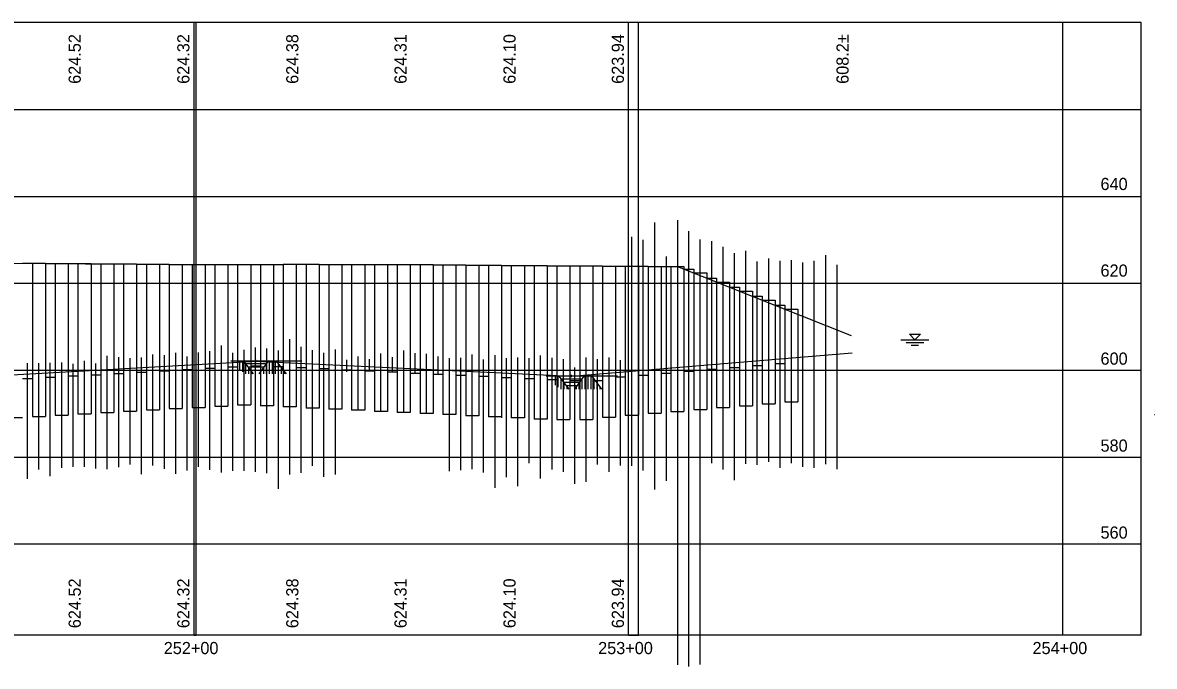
# Model space of a CAD drawing. Extents: x 2267596 to 2268160, y 713755 to 714793.
# Drawn here: x 2267899.2 to 2268159.8, y 713755.1 to 713903.3 of the extents above; entities that cross this region are included whole.
import ezdxf

# ---------------------------------------------------------------- set-up
doc = ezdxf.new("R2010")
doc.units = 0
for name, color, linetype in [('BR_P_Gen_Text', 7, 'Continuous'), ('BR_P_Sub_Deep_Object', 7, 'Continuous'), ('Default', 7, 'Continuous'), ('GE_X_Alignment', 7, 'Continuous'), ('PF_X_Ground_Line', 7, 'Continuous'), ('SC_Scratch1', 7, 'Continuous'), ('SC_Scratch3', 7, 'Continuous'), ('SC_Scratch9', 7, 'Continuous'), ('SH_Major_Grid_Line', 7, 'Continuous'), ('UT_P_Water_Cells', 7, 'Continuous'), ('XS_X_Ground_Line', 7, 'Continuous')]:
    doc.layers.add(name, color=color, linetype=linetype)

msp = doc.modelspace()

# ---------------------------------------------------------------- linework, layer by layer
at = {"layer": 'BR_P_Sub_Deep_Object'}
for p, q in [((2267899.24, 713847.93), (2267901.49, 713847.93)), ((2267901.49, 713847.93), (2267901.49, 713812.68)), ((2267901.49, 713847.92), (2267904.49, 713847.92)), ((2267904.49, 713847.92), (2267904.49, 713812.68)), ((2267904.49, 713847.9), (2267906.74, 713847.9)), ((2267906.74, 713847.9), (2267906.74, 713812.98)), ((2267906.74, 713847.88), (2267909.74, 713847.88)), ((2267909.74, 713847.88), (2267909.74, 713812.98)), ((2267909.74, 713847.86), (2267911.99, 713847.86)), ((2267911.99, 713847.86), (2267911.99, 713813.27)), ((2267911.99, 713847.85), (2267914.99, 713847.85)), ((2267914.99, 713847.85), (2267914.99, 713813.27)), ((2267914.99, 713847.82), (2267917.24, 713847.82)), ((2267917.24, 713847.82), (2267917.24, 713813.57)), ((2267917.24, 713847.81), (2267920.24, 713847.81)), ((2267920.24, 713847.81), (2267920.24, 713813.57)), ((2267920.24, 713847.78), (2267922.49, 713847.78)), ((2267922.49, 713847.78), (2267922.49, 713813.87)), ((2267922.49, 713847.76), (2267925.49, 713847.76)), ((2267925.49, 713847.76), (2267925.49, 713813.87)), ((2267925.49, 713847.74), (2267927.74, 713847.74)), ((2267927.74, 713847.74), (2267927.74, 713814.16)), ((2267927.74, 713847.72), (2267930.74, 713847.72)), ((2267930.74, 713847.72), (2267930.74, 713814.16)), ((2267930.74, 713847.7), (2267932.99, 713847.7)), ((2267932.99, 713847.7), (2267932.99, 713814.46)), ((2267932.99, 713847.68), (2267935.99, 713847.68)), ((2267935.99, 713847.68), (2267935.99, 713814.46)), ((2267935.99, 713847.66), (2267938.24, 713847.66)), ((2267938.24, 713847.66), (2267938.24, 713814.75)), ((2267938.24, 713847.64), (2267941.24, 713847.64)), ((2267941.24, 713847.64), (2267941.24, 713814.75)), ((2267941.24, 713847.64), (2267943.49, 713847.64)), ((2267943.49, 713847.65), (2267943.49, 713815.05)), ((2267943.49, 713847.65), (2267946.49, 713847.65)), ((2267946.49, 713847.66), (2267946.49, 713815.05)), ((2267946.49, 713847.66), (2267948.74, 713847.66)), ((2267948.74, 713847.66), (2267948.74, 713815.34)), ((2267948.74, 713847.66), (2267951.74, 713847.66)), ((2267951.74, 713847.67), (2267951.74, 713815.34)), ((2267951.74, 713847.67), (2267953.99, 713847.67)), ((2267953.99, 713847.68), (2267953.99, 713815.11)), ((2267953.99, 713847.68), (2267956.99, 713847.68)), ((2267956.99, 713847.68), (2267956.99, 713815.11)), ((2267956.99, 713847.68), (2267959.24, 713847.68)), ((2267959.24, 713847.69), (2267959.24, 713814.86)), ((2267959.24, 713847.69), (2267962.24, 713847.69)), ((2267962.24, 713847.69), (2267962.24, 713814.86)), ((2267962.24, 713847.69), (2267964.49, 713847.69)), ((2267964.49, 713847.69), (2267964.49, 713814.6)), ((2267964.49, 713847.69), (2267967.49, 713847.69)), ((2267967.49, 713847.69), (2267967.49, 713814.6)), ((2267967.49, 713847.68), (2267969.74, 713847.68)), ((2267969.74, 713847.68), (2267969.74, 713814.35)), ((2267969.74, 713847.68), (2267972.74, 713847.68)), ((2267972.74, 713847.68), (2267972.74, 713814.35)), ((2267972.74, 713847.67), (2267974.99, 713847.67)), ((2267974.99, 713847.67), (2267974.99, 713814.1)), ((2267974.99, 713847.66), (2267977.99, 713847.66)), ((2267977.99, 713847.66), (2267977.99, 713814.1)), ((2267977.99, 713847.65), (2267980.24, 713847.65)), ((2267980.24, 713847.65), (2267980.24, 713813.84)), ((2267980.24, 713847.65), (2267983.24, 713847.65)), ((2267983.24, 713847.65), (2267983.24, 713813.84)), ((2267983.24, 713847.64), (2267985.49, 713847.64)), ((2267985.49, 713847.64), (2267985.49, 713813.59)), ((2267985.49, 713847.63), (2267988.49, 713847.63)), ((2267988.49, 713847.63), (2267988.49, 713813.59)), ((2267988.49, 713847.62), (2267990.74, 713847.62)), ((2267990.74, 713847.62), (2267990.74, 713813.34)), ((2267990.74, 713847.61), (2267993.74, 713847.61)), ((2267993.74, 713847.61), (2267993.74, 713813.34)), ((2267993.74, 713847.58), (2267995.99, 713847.58)), ((2267995.99, 713847.58), (2267995.99, 713813.09)), ((2267995.99, 713847.56), (2267998.99, 713847.56)), ((2267998.99, 713847.56), (2267998.99, 713813.09)), ((2267998.99, 713847.54), (2268001.24, 713847.54)), ((2268001.24, 713847.54), (2268001.24, 713812.83)), ((2268001.24, 713847.52), (2268004.24, 713847.52)), ((2268004.24, 713847.52), (2268004.24, 713812.83)), ((2268004.24, 713847.49), (2268006.49, 713847.49)), ((2268006.49, 713847.49), (2268006.49, 713812.58)), ((2268006.49, 713847.47), (2268009.49, 713847.47)), ((2268009.49, 713847.47), (2268009.49, 713812.33)), ((2268009.49, 713847.45), (2268011.74, 713847.45)), ((2268011.74, 713847.45), (2268011.74, 713812.33)), ((2268011.74, 713847.43), (2268014.74, 713847.43)), ((2268014.74, 713847.43), (2268014.74, 713812.33)), ((2268014.74, 713847.41), (2268016.99, 713847.41)), ((2268016.99, 713847.41), (2268016.99, 713812.07)), ((2268016.99, 713847.39), (2268019.99, 713847.39)), ((2268019.99, 713847.39), (2268019.99, 713812.07)), ((2268019.99, 713847.37), (2268022.24, 713847.37)), ((2268022.24, 713847.37), (2268022.24, 713811.93)), ((2268022.24, 713847.36), (2268025.24, 713847.36)), ((2268025.24, 713847.36), (2268025.24, 713811.93)), ((2268025.24, 713847.34), (2268027.49, 713847.34)), ((2268027.49, 713847.34), (2268027.49, 713811.93)), ((2268027.49, 713847.33), (2268030.49, 713847.33)), ((2268030.49, 713847.33), (2268030.49, 713811.93)), ((2268030.49, 713847.31), (2268032.74, 713847.31)), ((2268032.74, 713847.31), (2268032.74, 713812.51)), ((2268032.74, 713847.29), (2268035.74, 713847.29)), ((2268035.74, 713847.29), (2268035.74, 713812.51)), ((2268035.74, 713847.27), (2268037.99, 713847.27)), ((2268037.99, 713847.27), (2268037.99, 713812.95)), ((2268037.99, 713847.26), (2268040.99, 713847.26)), ((2268040.99, 713847.26), (2268040.99, 713812.95)), ((2268040.99, 713847.24), (2268043.24, 713847.24)), ((2268043.24, 713847.24), (2268043.24, 713813.39)), ((2268043.24, 713847.22), (2268046.24, 713847.22)), ((2268046.24, 713847.22), (2268046.24, 713813.39)), ((2268046.24, 713847.21), (2268048.49, 713847.21)), ((2268048.49, 713847.21), (2268048.49, 713813.83)), ((2268048.49, 713847.18), (2268051.49, 713847.18)), ((2268051.49, 713847.18), (2268051.49, 713813.83)), ((2268051.49, 713846.59), (2268053.74, 713846.59)), ((2268053.74, 713846.59), (2268053.74, 713814.27)), ((2268053.74, 713845.69), (2268056.74, 713845.69)), ((2268056.74, 713845.69), (2268056.74, 713814.27)), ((2268056.74, 713844.5), (2268058.99, 713844.5)), ((2268058.99, 713844.5), (2268058.99, 713814.7)), ((2268058.99, 713843.61), (2268061.99, 713843.61)), ((2268061.99, 713843.61), (2268061.99, 713814.7)), ((2268061.99, 713842.42), (2268064.24, 713842.42)), ((2268064.24, 713842.42), (2268064.24, 713815.14)), ((2268064.24, 713841.53), (2268067.24, 713841.53)), ((2268067.24, 713841.53), (2268067.24, 713815.14)), ((2268067.24, 713840.34), (2268069.49, 713840.34)), ((2268069.49, 713840.34), (2268069.49, 713815.58)), ((2268069.49, 713839.45), (2268072.49, 713839.45)), ((2268072.49, 713839.45), (2268072.49, 713815.58)), ((2268072.49, 713838.26), (2268074.74, 713838.26)), ((2268074.74, 713838.26), (2268074.74, 713816.02)), ((2268074.74, 713837.36), (2268077.74, 713837.36)), ((2268077.74, 713837.36), (2268077.74, 713816.02)), ((2268072.49, 713824.83), (2268074.74, 713824.83)), ((2267909.74, 713821.98), (2267911.99, 713821.98)), ((2267914.99, 713822.27), (2267917.24, 713822.27)), ((2267920.24, 713822.57), (2267922.49, 713822.57)), ((2267925.49, 713822.87), (2267927.74, 713822.87)), ((2267930.74, 713823.16), (2267932.99, 713823.16)), ((2267935.99, 713823.46), (2267938.24, 713823.46)), ((2267941.24, 713823.75), (2267943.49, 713823.75)), ((2267946.49, 713824.05), (2267948.74, 713824.05)), ((2267951.74, 713824.34), (2267953.99, 713824.34)), ((2267959.24, 713824.11), (2267956.99, 713824.11)), ((2267964.49, 713823.86), (2267962.24, 713823.86)), ((2267969.74, 713823.6), (2267967.49, 713823.6)), ((2267974.99, 713823.35), (2267972.74, 713823.35)), ((2267980.24, 713823.1), (2267977.99, 713823.1)), ((2267985.49, 713822.84), (2267983.24, 713822.84)), ((2267990.74, 713822.59), (2267988.49, 713822.59)), ((2267995.99, 713822.34), (2267993.74, 713822.34)), ((2268001.24, 713822.09), (2267998.99, 713822.09)), ((2268040.99, 713822.2), (2268043.24, 713822.2)), ((2268046.24, 713822.64), (2268048.49, 713822.64)), ((2268051.49, 713823.08), (2268053.74, 713823.08)), ((2268056.74, 713823.52), (2268058.99, 713823.52)), ((2268061.99, 713823.96), (2268064.24, 713823.96)), ((2268067.24, 713824.39), (2268069.49, 713824.39)), ((2267899.24, 713821.39), (2267901.49, 713821.39)), ((2267904.49, 713821.68), (2267906.74, 713821.68)), ((2268006.49, 713821.83), (2268004.24, 713821.83)), ((2268011.74, 713821.58), (2268009.49, 713821.58)), ((2268016.99, 713821.33), (2268014.74, 713821.33)), ((2268022.24, 713821.07), (2268019.99, 713821.07)), ((2268025.24, 713820.93), (2268027.49, 713820.93)), ((2268030.49, 713820.93), (2268032.74, 713820.93)), ((2268035.74, 713821.76), (2268037.99, 713821.76)), ((2267927.74, 713814.16), (2267930.74, 713814.16)), ((2267932.99, 713814.46), (2267935.99, 713814.46)), ((2267938.24, 713814.75), (2267941.24, 713814.75)), ((2267943.49, 713815.05), (2267946.49, 713815.05)), ((2267948.74, 713815.34), (2267951.74, 713815.34)), ((2267956.99, 713815.11), (2267953.99, 713815.11)), ((2267962.24, 713814.86), (2267959.24, 713814.86)), ((2267967.49, 713814.6), (2267964.49, 713814.6)), ((2267972.74, 713814.35), (2267969.74, 713814.35)), ((2268053.74, 713814.27), (2268056.74, 713814.27)), ((2268058.99, 713814.7), (2268061.99, 713814.7)), ((2268064.24, 713815.14), (2268067.24, 713815.14)), ((2268069.49, 713815.58), (2268072.49, 713815.58)), ((2268074.74, 713816.02), (2268077.74, 713816.02)), ((2267896.24, 713812.39), (2267899.24, 713812.39)), ((2267901.49, 713812.68), (2267904.49, 713812.68)), ((2267906.74, 713812.98), (2267909.74, 713812.98)), ((2267911.99, 713813.27), (2267914.99, 713813.27)), ((2267917.24, 713813.57), (2267920.24, 713813.57)), ((2267922.49, 713813.87), (2267925.49, 713813.87)), ((2267977.99, 713814.1), (2267974.99, 713814.1)), ((2267983.24, 713813.84), (2267980.24, 713813.84)), ((2267988.49, 713813.59), (2267985.49, 713813.59)), ((2267993.74, 713813.34), (2267990.74, 713813.34)), ((2267998.99, 713813.09), (2267995.99, 713813.09)), ((2268004.24, 713812.83), (2268001.24, 713812.83)), ((2268009.49, 713812.58), (2268006.49, 713812.58)), ((2268014.74, 713812.33), (2268011.74, 713812.33)), ((2268019.99, 713812.07), (2268016.99, 713812.07)), ((2268022.24, 713811.93), (2268025.24, 713811.93)), ((2268027.49, 713811.93), (2268030.49, 713811.93)), ((2268032.74, 713812.51), (2268035.74, 713812.51)), ((2268037.99, 713812.95), (2268040.99, 713812.95)), ((2268043.24, 713813.39), (2268046.24, 713813.39)), ((2268048.49, 713813.83), (2268051.49, 713813.83))]:
    msp.add_line(p, q, dxfattribs=at)
at = {"layer": 'Default'}
for p, q in [((2267963.53, 713825.41), (2267947.14, 713825.41)), ((2267949.16, 713825.41), (2267949.16, 713823.35)), ((2267949.85, 713825.41), (2267949.85, 713822.92)), ((2267950.06, 713825.41), (2267952.34, 713822.46)), ((2267950.54, 713824.8), (2267950.54, 713822.46)), ((2267955.31, 713824.77), (2267950.54, 713824.77)), ((2267955.77, 713825.41), (2267953.64, 713822.46)), ((2267955.31, 713824.77), (2267955.31, 713822.46)), ((2267956, 713825.41), (2267956, 713822.46)), ((2267956.69, 713825.41), (2267956.69, 713822.46)), ((2267957.38, 713825.41), (2267957.38, 713822.46)), ((2267957.6, 713825.41), (2267959.88, 713822.46)), ((2267958.07, 713824.8), (2267958.07, 713822.46)), ((2267954.76, 713824.01), (2267951.14, 713824.01)), ((2267951.23, 713823.9), (2267951.23, 713822.46)), ((2267954.19, 713823.22), (2267951.75, 713823.22)), ((2267951.91, 713823.02), (2267951.91, 713822.46)), ((2267954.01, 713822.97), (2267954.01, 713822.46)), ((2267954.66, 713823.87), (2267954.66, 713822.46)), ((2267958.76, 713823.9), (2267958.76, 713822.46)), ((2267959.45, 713823.02), (2267959.45, 713822.46)), ((2268036.18, 713821.91), (2268019.79, 713821.91)), ((2268021.8, 713821.91), (2268021.8, 713819.85)), ((2268022.49, 713821.91), (2268022.49, 713819.42)), ((2268022.71, 713821.91), (2268024.99, 713818.96)), ((2268023.18, 713821.3), (2268023.18, 713818.96)), ((2268027.96, 713821.27), (2268023.18, 713821.27)), ((2268027.4, 713820.51), (2268023.79, 713820.51)), ((2268023.87, 713820.4), (2268023.87, 713818.96)), ((2268026.83, 713819.72), (2268024.4, 713819.72)), ((2268024.56, 713819.52), (2268024.56, 713818.96)), ((2268028.42, 713821.91), (2268026.28, 713818.96)), ((2268026.65, 713819.47), (2268026.65, 713818.96)), ((2268027.3, 713820.37), (2268027.3, 713818.96)), ((2268027.96, 713821.27), (2268027.96, 713818.96)), ((2268028.65, 713821.91), (2268028.65, 713818.96)), ((2268029.34, 713821.91), (2268029.34, 713818.96)), ((2268030.03, 713821.91), (2268030.03, 713818.96)), ((2268030.25, 713821.91), (2268032.52, 713818.96)), ((2268030.72, 713821.3), (2268030.72, 713818.96)), ((2268031.41, 713820.4), (2268031.41, 713818.96)), ((2268032.09, 713819.52), (2268032.09, 713818.96))]:
    msp.add_line(p, q, dxfattribs=at)
at = {"layer": 'GE_X_Alignment'}
for p, q in [((2267938.74, 713762.33), (2267938.74, 713903.31)), ((2268038.74, 713762.33), (2268038.74, 713903.31)), ((2268138.74, 713762.33), (2268138.74, 713903.31)), ((2267595.7, 713883.31), (2268156.77, 713883.31)), ((2267595.7, 713863.31), (2268156.77, 713863.31)), ((2267595.7, 713843.31), (2268156.77, 713843.31)), ((2267595.7, 713823.31), (2268156.77, 713823.31)), ((2267595.7, 713803.31), (2268156.77, 713803.31)), ((2267595.7, 713783.31), (2268156.77, 713783.31))]:
    msp.add_line(p, q, dxfattribs=at)
at = {"layer": 'PF_X_Ground_Line'}
msp.add_line((2268159.73, 713813.12), (2268159.78, 713813.12), dxfattribs=at)
at = {"layer": 'SC_Scratch1'}
for p, q in [((2268044.74, 713857.29), (2268044.74, 713795.88)), ((2268049.99, 713857.86), (2268049.99, 713755.47)), ((2268039.49, 713801.27), (2268039.49, 713854)), ((2268042.12, 713800.26), (2268042.12, 713853.32)), ((2268052.62, 713755.14), (2268052.62, 713855.34)), ((2268055.24, 713755.59), (2268055.24, 713853.42)), ((2268057.87, 713801.92), (2268057.87, 713853.02)), ((2268060.49, 713800.48), (2268060.49, 713851.68)), ((2268065.74, 713801.77), (2268065.74, 713850.75)), ((2268047.37, 713849.46), (2268047.37, 713797.82)), ((2268063.12, 713797.98), (2268063.12, 713850.22)), ((2268068.37, 713801.55), (2268068.37, 713848.35)), ((2268070.99, 713802.23), (2268070.99, 713849.02)), ((2268073.62, 713800.86), (2268073.62, 713848.48)), ((2268076.24, 713801.88), (2268076.24, 713848.62)), ((2268078.87, 713801.08), (2268078.87, 713848.08)), ((2268081.49, 713800.83), (2268081.49, 713848.48)), ((2268084.12, 713801.68), (2268084.12, 713849.82)), ((2268086.74, 713800.54), (2268086.74, 713847.55)), ((2267960.74, 713799.28), (2267960.74, 713830.44)), ((2267934.49, 713799.49), (2267934.49, 713827.3)), ((2267939.74, 713801.05), (2267939.74, 713827.35)), ((2267942.37, 713800.35), (2267942.37, 713827.67)), ((2267944.99, 713799.8), (2267944.99, 713829.03)), ((2267947.62, 713800.17), (2267947.62, 713827.33)), ((2267950.24, 713800.17), (2267950.24, 713828.02)), ((2267952.87, 713799.89), (2267952.87, 713828.5)), ((2267955.49, 713799.62), (2267955.49, 713828.29)), ((2267958.12, 713795.99), (2267958.12, 713827.83)), ((2267963.37, 713799.66), (2267963.37, 713828.71)), ((2267965.99, 713801.28), (2267965.99, 713827.92)), ((2267968.62, 713798.78), (2267968.62, 713827.3)), ((2267971.24, 713799.28), (2267971.24, 713828.07)), ((2267986.99, 713813.59), (2267986.99, 713827.81)), ((2267989.62, 713822.59), (2267989.62, 713827.26)), ((2267900.37, 713798.29), (2267900.37, 713824.9)), ((2267902.99, 713800.47), (2267902.99, 713824.9)), ((2267905.62, 713798.89), (2267905.62, 713825.01)), ((2267908.24, 713800.85), (2267908.24, 713825.11)), ((2267910.87, 713801.04), (2267910.87, 713824.74)), ((2267913.49, 713801.07), (2267913.49, 713825.48)), ((2267916.12, 713800.71), (2267916.12, 713824.85)), ((2267918.74, 713800.53), (2267918.74, 713826.61)), ((2267921.37, 713801.02), (2267921.37, 713826.3)), ((2267923.99, 713801.64), (2267923.99, 713826.09)), ((2267926.62, 713799.36), (2267926.62, 713826.25)), ((2267929.24, 713801.39), (2267929.24, 713826.93)), ((2267931.87, 713800.59), (2267931.87, 713826.77)), ((2267937.12, 713800.22), (2267937.12, 713826.46)), ((2267973.87, 713822.96), (2267973.87, 713825.72)), ((2267976.49, 713814.1), (2267976.49, 713826.48)), ((2267979.12, 713823.1), (2267979.12, 713825.85)), ((2267981.74, 713813.84), (2267981.74, 713827.17)), ((2267984.37, 713822.84), (2267984.37, 713826.33)), ((2267992.24, 713813.34), (2267992.24, 713827.08)), ((2267994.87, 713822.34), (2267994.87, 713826.44)), ((2267997.49, 713800.1), (2267997.49, 713826.07)), ((2268000.12, 713800.28), (2268000.12, 713826.16)), ((2268002.74, 713800.56), (2268002.74, 713826.9)), ((2268005.37, 713799.76), (2268005.37, 713825.8)), ((2268007.99, 713796.27), (2268007.99, 713826.8)), ((2268010.62, 713798.7), (2268010.62, 713826.07)), ((2268013.24, 713796.64), (2268013.24, 713826.25)), ((2268015.87, 713801.9), (2268015.87, 713826.07)), ((2268018.49, 713798.38), (2268018.49, 713826.71)), ((2268021.12, 713800.46), (2268021.12, 713826.15)), ((2268023.74, 713799.93), (2268023.74, 713825.89)), ((2268028.99, 713797.62), (2268028.99, 713826.24)), ((2268031.62, 713801.62), (2268031.62, 713825.87)), ((2268034.24, 713799.91), (2268034.24, 713826.27)), ((2268036.87, 713801.34), (2268036.87, 713825.61)), ((2268026.37, 713797.19), (2268026.37, 713823.91))]:
    msp.add_line(p, q, dxfattribs=at)
at = {"layer": 'SC_Scratch3'}
for p, q in [((2267939.21, 713762.33), (2267939.21, 713903.31)), ((2268041.06, 713762.33), (2268041.06, 713903.31)), ((2267938.74, 713762.33), (2267939.21, 713762.33)), ((2268038.74, 713762.33), (2268041.06, 713762.33))]:
    msp.add_line(p, q, dxfattribs=at)
at = {"layer": 'SC_Scratch9'}
for p, q in [((2267952.95, 713825.19), (2267952.95, 713825.72)), ((2268025.6, 713821.69), (2268025.6, 713822.22))]:
    msp.add_line(p, q, dxfattribs=at)
at = {"layer": 'SH_Major_Grid_Line'}
for p, q in [((2268156.77, 713903.31), (2267595.7, 713903.31)), ((2268156.77, 713762.33), (2268156.77, 713903.31)), ((2268156.77, 713762.33), (2267595.7, 713762.33))]:
    msp.add_line(p, q, dxfattribs=at)
at = {"layer": 'UT_P_Water_Cells'}
for p, q in [((2268101.42, 713830.31), (2268107.89, 713830.31)), ((2268104.66, 713830.31), (2268103.39, 713831.58)), ((2268103.39, 713831.58), (2268105.92, 713831.58)), ((2268104.66, 713830.31), (2268105.92, 713831.58)), ((2268102.62, 713829.71), (2268106.69, 713829.71)), ((2268103.82, 713829.11), (2268105.49, 713829.11))]:
    msp.add_line(p, q, dxfattribs=at)
at = {"layer": 'XS_X_Ground_Line'}
for p, q in [((2268049.99, 713847.18), (2268090, 713831.31)), ((2268025.6, 713821.91), (2268090.2, 713827.31))]:
    msp.add_line(p, q, dxfattribs=at)
for points in [[(2267638.74, 713849.74), (2267663.74, 713849.7), (2267688.74, 713849.68), (2267713.74, 713849.46), (2267738.74, 713849.22), (2267788.74, 713848.72), (2267813.74, 713848.56), (2267838.74, 713848.39), (2267863.74, 713848.15), (2267888.74, 713848), (2267913.74, 713847.83), (2267938.74, 713847.63), (2267963.74, 713847.69), (2267988.74, 713847.62), (2268013.74, 713847.41), (2268049.99, 713847.18)], [(2267694.36, 713823.21), (2267751.31, 713826.51), (2267874.79, 713821.01), (2267952.95, 713825.41), (2268025.6, 713821.91)]]:
    msp.add_lwpolyline(points, dxfattribs=at)

# ---------------------------------------------------------------- texts
at = {"layer": 'BR_P_Gen_Text'}
for s, p in [('624.52', (2267912.63, 713889.22)), ('624.32', (2267937.64, 713889.22)), ('624.38', (2267962.72, 713889.22)), ('624.31', (2267987.64, 713889.22)), ('624.10', (2268012.72, 713889.22)), ('623.94', (2268037.66, 713889.22)), ('608.2±', (2268089.4, 713889.22)), ('624.52', (2267912.63, 713763.93)), ('624.32', (2267937.64, 713763.93)), ('624.38', (2267962.72, 713763.93)), ('624.31', (2267987.64, 713763.93)), ('624.10', (2268012.72, 713763.93)), ('623.94', (2268037.66, 713763.93))]:
    msp.add_text(s, height=2.8, rotation=90, dxfattribs=at).set_placement(p)
for s, p in [('640', (2268147.38, 713864.78)), ('620', (2268147.38, 713844.85)), ('600', (2268147.38, 713824.58)), ('580', (2268147.38, 713804.56)), ('560', (2268147.38, 713784.54)), ('252+00', (2267931.73, 713757.96)), ('253+00', (2268031.73, 713757.96)), ('254+00', (2268131.73, 713757.96))]:
    msp.add_text(s, height=2.8, dxfattribs=at).set_placement(p)

doc.saveas('drawing.dxf')
